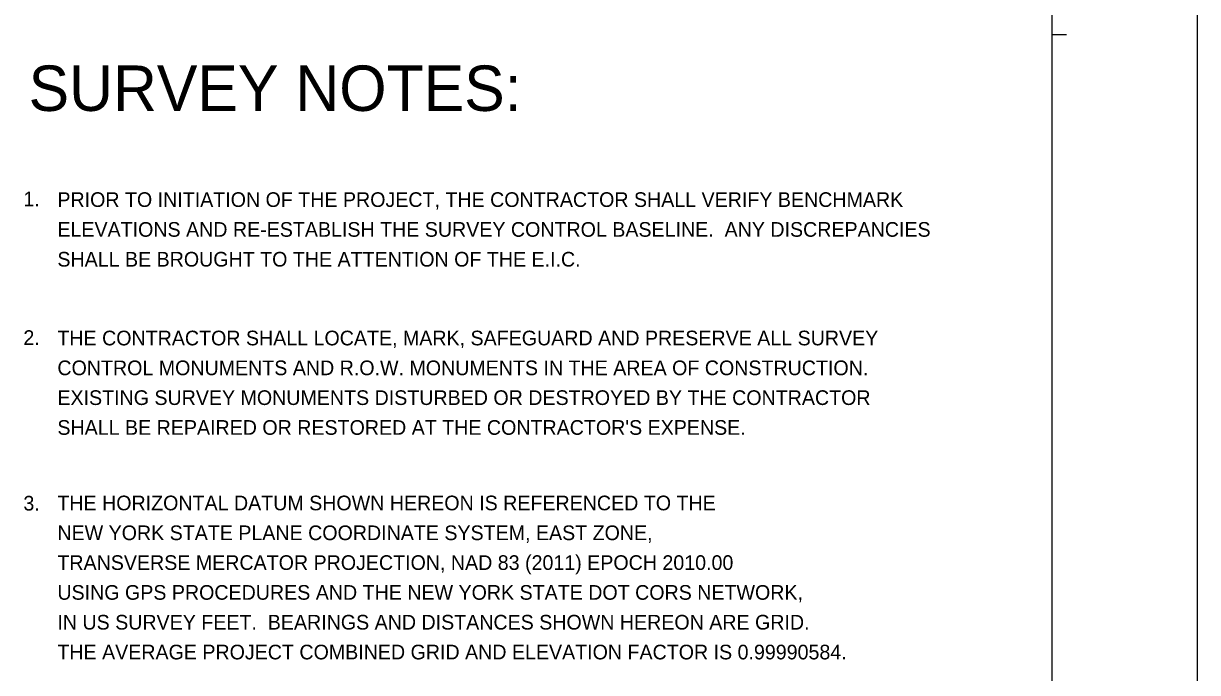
# Model space of a CAD drawing. Extents: x 359002 to 361405, y 1522603 to 1525369.
# Drawn here: x 361001.8 to 361404.8, y 1522823.9 to 1523046.7 of the extents above; entities that cross this region are included whole.
import ezdxf

# ---------------------------------------------------------------- set-up
doc = ezdxf.new("R2010")
doc.units = 0
for name, color, linetype in [('Default', 7, 'Continuous'), ('Manuscript', 7, 'Continuous'), ('SHEET_BORDER', 7, 'Continuous'), ('SHEET_BORDER_EDGE', 7, 'Continuous')]:
    doc.layers.add(name, color=color, linetype=linetype)

msp = doc.modelspace()

# ---------------------------------------------------------------- linework, layer by layer
at = {"layer": 'SHEET_BORDER'}
msp.add_line((361354.78, 1523042.89), (361359.78, 1523042.89), dxfattribs=at)
msp.add_lwpolyline([(361354.78, 1522628.52), (361349.78, 1522623.52), (360099.78, 1522623.52), (360094.78, 1522628.52), (360094.78, 1523457.27), (360099.78, 1523462.27), (361349.78, 1523462.27), (361354.78, 1523457.27)], close=True, dxfattribs=at)
at = {"layer": 'SHEET_BORDER_EDGE'}
msp.add_lwpolyline([(360044.78, 1522602.9), (361404.78, 1522602.9), (361404.78, 1523482.89), (360044.78, 1523482.89)], close=True, dxfattribs=at)

# ---------------------------------------------------------------- texts
at = {"layer": 'Default'}
msp.add_text('SURVEY NOTES:', height=15.6, dxfattribs=at).set_placement((361003.52, 1523016.67))
at = {"layer": 'Manuscript'}
for s, height, p in [('1.', 5.036, (361001.74, 1522983.95)), ('PRIOR TO INITIATION OF THE PROJECT, THE CONTRACTOR SHALL VERIFY BENCHMARK', 5.0361, (361013.41, 1522983.71)), ('ELEVATIONS AND RE-ESTABLISH THE SURVEY CONTROL BASELINE.  ANY DISCREPANCIES', 5.0361, (361013.41, 1522973.47)), ('SHALL BE BROUGHT TO THE ATTENTION OF THE E.I.C.', 5.0361, (361013.41, 1522963.24)), ('2.', 5.036, (361001.74, 1522936.34)), ('THE CONTRACTOR SHALL LOCATE, MARK, SAFEGUARD AND PRESERVE ALL SURVEY', 5.0361, (361013.41, 1522936.19)), ('CONTROL MONUMENTS AND R.O.W. MONUMENTS IN THE AREA OF CONSTRUCTION.', 5.0361, (361013.41, 1522925.95)), ('EXISTING SURVEY MONUMENTS DISTURBED OR DESTROYED BY THE CONTRACTOR', 5.0361, (361013.41, 1522915.72)), ("SHALL BE REPAIRED OR RESTORED AT THE CONTRACTOR'S EXPENSE. ", 5.0361, (361013.41, 1522905.48)), ('3.', 5.036, (361001.74, 1522879.48)), ('THE HORIZONTAL DATUM SHOWN HEREON IS REFERENCED TO THE ', 5.0361, (361013.41, 1522879.56)), ('NEW YORK STATE PLANE COORDINATE SYSTEM, EAST ZONE, ', 5.0361, (361013.41, 1522869.32)), ('TRANSVERSE MERCATOR PROJECTION, NAD 83 (2011) EPOCH 2010.00', 5.0361, (361013.41, 1522859.09)), ('USING GPS PROCEDURES AND THE NEW YORK STATE DOT CORS NETWORK,', 5.0361, (361013.41, 1522848.85)), ('IN US SURVEY FEET.  BEARINGS AND DISTANCES SHOWN HEREON ARE GRID.', 5.0361, (361013.41, 1522838.62)), ('THE AVERAGE PROJECT COMBINED GRID AND ELEVATION FACTOR IS 0.99990584.', 5.0361, (361013.41, 1522828.38))]:
    msp.add_text(s, height=height, dxfattribs=at).set_placement(p)

doc.saveas('drawing.dxf')
